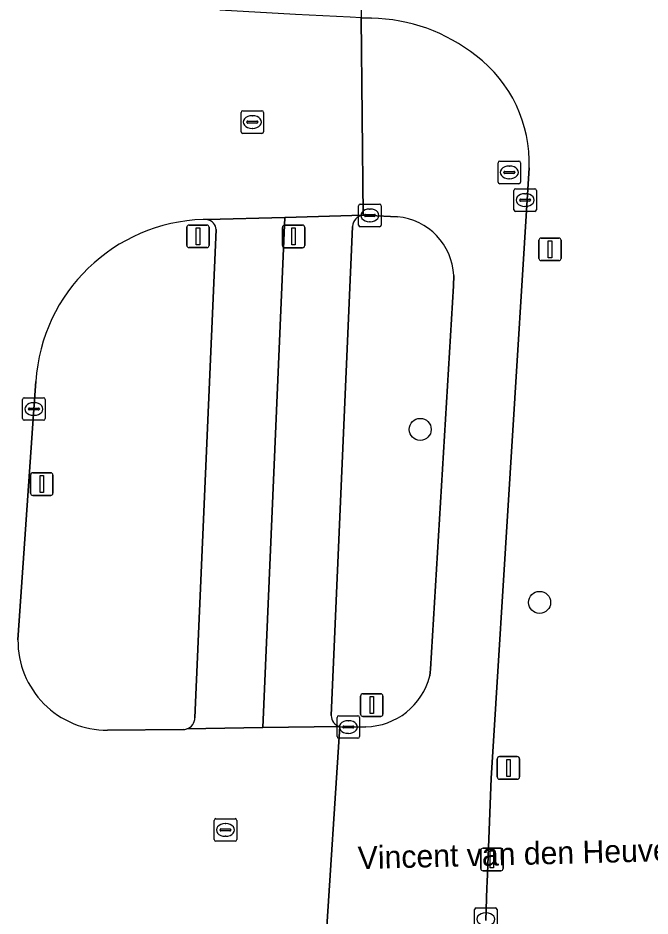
# Model space of a CAD drawing. Extents: x 161477 to 163040, y 383680 to 384871.
# Drawn here: x 161516.43 to 161544.45, y 384118.32 to 384158.1 of the extents above; entities that cross this region are included whole.
import ezdxf

# ---------------------------------------------------------------- set-up
doc = ezdxf.new("R2010")
doc.units = 0
for name, color, linetype in [('IMGEO_Afsluitpaal', 7, 'Continuous'), ('IMGEO_Boom', 7, 'Continuous'), ('IMGEO_Fietspad_open', 7, 'Continuous'), ('IMGEO_Groenvoorziening', 7, 'Continuous'), ('IMGEO_Kolk', 7, 'Continuous'), ('IMGEO_Lichtmast', 7, 'Continuous'), ('IMGEO_Openbare_ruimte_label', 7, 'Continuous'), ('IMGEO_Rijbaan_lokaal_gesloten', 7, 'Continuous'), ('IMGEO_Rioolput', 7, 'Continuous'), ('IMGEO_Verkeersbordpaal', 7, 'Continuous'), ('IMGEO_Verkeerseiland_groen', 7, 'Continuous'), ('IMGEO_Vlaggenmast', 7, 'Continuous'), ('IMGEO_Voetpad_open', 7, 'Continuous')]:
    doc.layers.add(name, color=color, linetype=linetype)

msp = doc.modelspace()

# ---------------------------------------------------------------- linework, layer by layer
at = {"layer": 'IMGEO_Afsluitpaal'}
for p, q in [((161537.045, 384121.33), (161537.835, 384121.33)), ((161537.835, 384121.33), (161537.045, 384121.33)), ((161536.945, 384120.43), (161536.945, 384121.23)), ((161536.945, 384121.23), (161536.945, 384120.43)), ((161537.935, 384121.23), (161537.935, 384120.43)), ((161537.935, 384120.43), (161537.935, 384121.23)), ((161537.835, 384120.33), (161537.045, 384120.33)), ((161537.045, 384120.33), (161537.835, 384120.33))]:
    msp.add_line(p, q, dxfattribs=at)
msp.add_lwpolyline([(161537.365, 384121.205), (161537.515, 384121.205), (161537.515, 384120.455), (161537.365, 384120.455), (161537.365, 384121.205)], dxfattribs=at)
for centre, start, end in [((161537.045, 384121.23), 90, 180), ((161537.045, 384121.23), 90, 180), ((161537.835, 384121.23), 0, 90), ((161537.835, 384121.23), 360, 90), ((161537.045, 384120.43), 180, 270), ((161537.045, 384120.43), 180, 270), ((161537.835, 384120.43), 270, 0), ((161537.835, 384120.43), 270, 0)]:
    msp.add_arc(centre, 0.1, start, end, dxfattribs=at)
at = {"layer": 'IMGEO_Boom'}
for centre in [(161534.259, 384139.873), (161539.548, 384132.212)]:
    msp.add_circle(centre, 0.489, dxfattribs=at)
at = {"layer": 'IMGEO_Fietspad_open'}
for points in [[(161523.918, 384126.609), (161527.282, 384126.677), (161528.268, 384149.264)], [(161528.268, 384149.264), (161524.815, 384149.17)], [(161525.225, 384148.724), (161524.274, 384127.108)]]:
    msp.add_lwpolyline(points, dxfattribs=at)
for centre, radius, start, end in [((161524.716, 384148.668), 0.512, 6.3303, 78.8532), ((161523.751, 384127.105), 0.523, 288.6131, 0.3768)]:
    msp.add_arc(centre, radius, start, end, dxfattribs=at)
at = {"layer": 'IMGEO_Groenvoorziening'}
for points in [[(161628.281, 384137.114), (161624.648, 384135.722), (161619.424, 384134.087), (161616.059, 384133.366), (161612.429, 384132.961), (161606.375, 384132.939), (161598.545, 384133.672), (161592.268, 384135.114), (161586.623, 384137.484), (161581.539, 384140.473), (161576.425, 384143.894), (161572.308, 384147.016), (161565.467, 384151.61), (161561.106, 384153.825), (161556.746, 384155.662), (161551.068, 384157.566), (161545.8, 384159.194), (161540.797, 384160.153), (161534.39, 384160.217), (161531.691, 384160.176), (161531.642, 384158.109), (161532.1, 384158.086)], [(161539.082, 384151.455), (161537.405, 384124.413), (161537.225, 384119.825), (161537.21, 384119.595), (161537.167, 384118.119)]]:
    msp.add_lwpolyline(points, dxfattribs=at)
for centre, radius, start, end in [((161531.982, 384150.476), 7.611, 51.3377, 89.1153), ((161533.182, 384151.704), 5.906, 357.5883, 52.9839)]:
    msp.add_arc(centre, radius, start, end, dxfattribs=at)
at = {"layer": 'IMGEO_Kolk'}
for p, q in [((161538.41, 384149.606), (161538.41, 384150.458)), ((161538.485, 384150.532), (161539.337, 384150.532)), ((161538.898, 384150.312), (161538.923, 384150.312)), ((161539.411, 384150.458), (161539.411, 384149.606)), ((161538.669, 384150.026), (161538.669, 384150.038)), ((161539.107, 384149.989), (161538.709, 384149.989)), ((161538.712, 384150.075), (161539.11, 384150.075)), ((161539.153, 384150.038), (161539.153, 384150.026)), ((161531.529, 384148.927), (161531.529, 384149.779)), ((161531.604, 384149.853), (161532.456, 384149.853)), ((161532.017, 384149.633), (161532.042, 384149.633)), ((161532.53, 384149.779), (161532.53, 384148.927)), ((161539.337, 384149.532), (161538.485, 384149.532)), ((161538.921, 384149.752), (161538.896, 384149.752)), ((161531.788, 384149.347), (161531.788, 384149.359)), ((161532.226, 384149.31), (161531.828, 384149.31)), ((161531.831, 384149.396), (161532.229, 384149.396)), ((161532.272, 384149.359), (161532.272, 384149.347)), ((161532.456, 384148.853), (161531.604, 384148.853)), ((161532.04, 384149.073), (161532.015, 384149.073)), ((161516.639, 384140.353), (161516.639, 384141.205)), ((161516.714, 384141.279), (161517.566, 384141.279)), ((161517.64, 384141.205), (161517.64, 384140.353)), ((161516.898, 384140.773), (161516.898, 384140.785)), ((161517.336, 384140.736), (161516.938, 384140.736)), ((161516.941, 384140.822), (161517.339, 384140.822)), ((161517.127, 384141.059), (161517.152, 384141.059)), ((161517.382, 384140.785), (161517.382, 384140.773)), ((161517.15, 384140.499), (161517.125, 384140.499)), ((161517.566, 384140.279), (161516.714, 384140.279)), ((161530.574, 384126.269), (161530.574, 384127.121)), ((161530.649, 384127.195), (161531.501, 384127.195)), ((161531.062, 384126.975), (161531.087, 384126.975)), ((161531.575, 384127.121), (161531.575, 384126.269)), ((161530.833, 384126.689), (161530.833, 384126.701)), ((161531.271, 384126.652), (161530.873, 384126.652)), ((161530.876, 384126.738), (161531.274, 384126.738)), ((161531.085, 384126.415), (161531.06, 384126.415)), ((161531.317, 384126.701), (161531.317, 384126.689)), ((161531.501, 384126.195), (161530.649, 384126.195)), ((161536.668, 384117.759), (161536.668, 384118.611)), ((161536.743, 384118.685), (161537.595, 384118.685)), ((161537.156, 384118.465), (161537.181, 384118.465)), ((161537.669, 384118.611), (161537.669, 384117.759))]:
    msp.add_line(p, q, dxfattribs=at)
for points in [[(161538.41, 384149.606), (161538.41, 384150.458)], [(161538.485, 384150.532), (161539.337, 384150.532)], [(161539.411, 384150.458), (161539.411, 384149.606)], [(161531.529, 384148.927), (161531.529, 384149.779)], [(161531.604, 384149.853), (161532.456, 384149.853)], [(161532.53, 384149.779), (161532.53, 384148.927)], [(161539.337, 384149.532), (161538.485, 384149.532)], [(161532.456, 384148.853), (161531.604, 384148.853)], [(161516.639, 384140.353), (161516.639, 384141.205)], [(161516.714, 384141.279), (161517.566, 384141.279)], [(161517.64, 384141.205), (161517.64, 384140.353)], [(161517.566, 384140.279), (161516.714, 384140.279)], [(161530.574, 384126.269), (161530.574, 384127.121)], [(161530.649, 384127.195), (161531.501, 384127.195)], [(161531.575, 384127.121), (161531.575, 384126.269)], [(161531.501, 384126.195), (161530.649, 384126.195)], [(161536.668, 384117.759), (161536.668, 384118.611)], [(161536.743, 384118.685), (161537.595, 384118.685)], [(161537.669, 384118.611), (161537.669, 384117.759)]]:
    msp.add_lwpolyline(points, dxfattribs=at)
for centre, radius, start, end in [((161538.487, 384150.456), 0.0765, 91.552, 178.448), ((161538.487, 384150.456), 0.0765, 91.552, 178.448), ((161539.335, 384150.456), 0.0765, 1.552, 88.448), ((161539.335, 384150.456), 0.0765, 1.552, 88.448), ((161538.709, 384150.035), 0.0403, 85.8775, 175.7526), ((161538.706, 384150.025), 0.0366, 178.938, 274.7102), ((161539.11, 384150.032), 0.043, 264.8664, 352.4533), ((161539.114, 384150.037), 0.0386, 1.7309, 96.639), ((161531.606, 384149.777), 0.0765, 91.552, 178.448), ((161531.606, 384149.777), 0.0765, 91.552, 178.448), ((161532.454, 384149.777), 0.0765, 1.552, 88.448), ((161532.454, 384149.777), 0.0765, 1.552, 88.448), ((161538.487, 384149.608), 0.0765, 181.552, 268.448), ((161538.487, 384149.608), 0.0765, 181.552, 268.448), ((161539.335, 384149.608), 0.0765, 271.552, 358.448), ((161539.335, 384149.608), 0.0765, 271.552, 358.448), ((161531.828, 384149.356), 0.0403, 85.8775, 175.7526), ((161531.825, 384149.346), 0.0366, 178.938, 274.7102), ((161532.229, 384149.353), 0.043, 264.8664, 352.4533), ((161532.233, 384149.358), 0.0386, 1.7309, 96.639), ((161531.606, 384148.929), 0.0765, 181.552, 268.448), ((161531.606, 384148.929), 0.0765, 181.552, 268.448), ((161532.454, 384148.929), 0.0765, 271.552, 358.448), ((161532.454, 384148.929), 0.0765, 271.552, 358.448), ((161516.716, 384141.203), 0.0765, 91.552, 178.448), ((161516.716, 384141.203), 0.0765, 91.552, 178.448), ((161517.564, 384141.203), 0.0765, 1.552, 88.448), ((161517.564, 384141.203), 0.0765, 1.552, 88.448), ((161516.938, 384140.782), 0.0403, 85.8775, 175.7526), ((161516.935, 384140.772), 0.0366, 178.938, 274.7102), ((161517.339, 384140.779), 0.043, 264.8664, 352.4533), ((161517.343, 384140.784), 0.0386, 1.7309, 96.639), ((161516.716, 384140.355), 0.0765, 181.552, 268.448), ((161516.716, 384140.355), 0.0765, 181.552, 268.448), ((161517.564, 384140.355), 0.0765, 271.552, 358.448), ((161517.564, 384140.355), 0.0765, 271.552, 358.448), ((161530.651, 384127.119), 0.0765, 91.552, 178.448), ((161530.651, 384127.119), 0.0765, 91.552, 178.448), ((161531.499, 384127.119), 0.0765, 1.552, 88.448), ((161531.499, 384127.119), 0.0765, 1.552, 88.448), ((161530.873, 384126.698), 0.0403, 85.8775, 175.7526), ((161530.87, 384126.688), 0.0366, 178.938, 274.7102), ((161531.274, 384126.695), 0.043, 264.8664, 352.4533), ((161531.278, 384126.7), 0.0386, 1.7309, 96.639), ((161530.651, 384126.271), 0.0765, 181.552, 268.448), ((161530.651, 384126.271), 0.0765, 181.552, 268.448), ((161531.499, 384126.271), 0.0765, 271.552, 358.448), ((161531.499, 384126.271), 0.0765, 271.552, 358.448), ((161536.745, 384118.609), 0.0765, 91.552, 178.448), ((161536.745, 384118.609), 0.0765, 91.552, 178.448), ((161537.593, 384118.609), 0.0765, 1.552, 88.448), ((161537.593, 384118.609), 0.0765, 1.552, 88.448)]:
    msp.add_arc(centre, radius, start, end, dxfattribs=at)
for centre, major_axis, ratio, start_param, end_param in [((161538.897, 384150.032), (-0.387, 0.002), 0.722429, 4.712389, 7.853982), ((161538.922, 384150.032), (-0.39, 0.002), 0.717154, 1.570796, 4.712389), ((161532.016, 384149.353), (-0.387, 0.002), 0.722429, 4.712389, 7.853982), ((161532.041, 384149.353), (-0.39, 0.002), 0.717154, 1.570796, 4.712389), ((161517.126, 384140.779), (-0.387, 0.002), 0.722429, 4.712389, 7.853982), ((161517.151, 384140.779), (-0.39, 0.002), 0.717154, 1.570796, 4.712389), ((161531.061, 384126.695), (-0.387, 0.002), 0.722429, 4.712389, 7.853982), ((161531.086, 384126.695), (-0.39, 0.002), 0.717154, 1.570796, 4.712389), ((161537.155, 384118.185), (-0.387, 0.002), 0.722429, 4.712389, 7.853982), ((161537.18, 384118.185), (-0.39, 0.002), 0.717154, 1.570796, 4.712389)]:
    msp.add_ellipse(centre, major_axis=major_axis, ratio=ratio, start_param=start_param, end_param=end_param, dxfattribs=at)
at = {"layer": 'IMGEO_Lichtmast'}
for p, q in [((161528.153, 384148.024), (161528.153, 384148.824)), ((161528.153, 384148.824), (161528.153, 384148.024)), ((161528.253, 384148.924), (161529.043, 384148.924)), ((161529.043, 384148.924), (161528.253, 384148.924)), ((161529.143, 384148.824), (161529.143, 384148.024)), ((161529.143, 384148.024), (161529.143, 384148.824)), ((161529.043, 384147.924), (161528.253, 384147.924)), ((161528.253, 384147.924), (161529.043, 384147.924)), ((161517.095, 384137.953), (161517.885, 384137.953)), ((161517.885, 384137.953), (161517.095, 384137.953)), ((161516.995, 384137.053), (161516.995, 384137.853)), ((161516.995, 384137.853), (161516.995, 384137.053)), ((161517.985, 384137.853), (161517.985, 384137.053)), ((161517.985, 384137.053), (161517.985, 384137.853)), ((161517.885, 384136.953), (161517.095, 384136.953)), ((161517.095, 384136.953), (161517.885, 384136.953))]:
    msp.add_line(p, q, dxfattribs=at)
for points in [[(161528.573, 384148.799), (161528.723, 384148.799), (161528.723, 384148.049), (161528.573, 384148.049), (161528.573, 384148.799)], [(161517.415, 384137.828), (161517.565, 384137.828), (161517.565, 384137.078), (161517.415, 384137.078), (161517.415, 384137.828)]]:
    msp.add_lwpolyline(points, dxfattribs=at)
for centre, start, end in [((161528.253, 384148.824), 90, 180), ((161528.253, 384148.824), 90, 180), ((161529.043, 384148.824), 0, 90), ((161529.043, 384148.824), 360, 90), ((161528.253, 384148.024), 180, 270), ((161528.253, 384148.024), 180, 270), ((161529.043, 384148.024), 270, 0), ((161529.043, 384148.024), 270, 0), ((161517.095, 384137.853), 90, 180), ((161517.095, 384137.853), 90, 180), ((161517.885, 384137.853), 0, 90), ((161517.885, 384137.853), 360, 90), ((161517.095, 384137.053), 180, 270), ((161517.095, 384137.053), 180, 270), ((161517.885, 384137.053), 270, 0), ((161517.885, 384137.053), 270, 0)]:
    msp.add_arc(centre, 0.1, start, end, dxfattribs=at)
at = {"layer": 'IMGEO_Rijbaan_lokaal_gesloten'}
for points in [[(161524.815, 384149.17), (161528.268, 384149.264), (161531.725, 384149.358), (161531.642, 384158.109), (161531.156, 384158.133), (161528.739, 384158.251), (161525.377, 384158.45)], [(161532.1, 384158.086), (161531.642, 384158.109), (161531.725, 384149.358), (161531.759, 384149.36), (161531.793, 384149.36), (161532.03, 384149.353), (161533.25, 384149.288)], [(161537.167, 384118.119), (161537.21, 384119.595), (161537.225, 384119.825), (161537.405, 384124.413), (161539.082, 384151.455)], [(161535.746, 384146.688), (161535.738, 384146.227), (161534.722, 384129.256), (161534.686, 384128.956)], [(161516.434, 384130.556), (161517.14, 384140.779), (161517.224, 384142.004)], [(161523.75, 384126.582), (161520.406, 384126.549)], [(161530.064, 384116.948), (161530.697, 384126.716), (161527.282, 384126.677), (161523.918, 384126.609)], [(161530.697, 384126.716), (161530.064, 384116.948)], [(161531.85, 384126.707), (161531.075, 384126.695), (161530.841, 384126.7)]]:
    msp.add_lwpolyline(points, dxfattribs=at)
for centre, radius, start, end in [((161531.982, 384150.476), 7.611, 51.3377, 89.1153), ((161533.182, 384151.704), 5.906, 357.5883, 52.9839), ((161524.896, 384141.489), 7.689, 91.8843, 176.1601), ((161524.717, 384148.647), 0.532, 79.3661, 97.9695), ((161533.014, 384146.564), 2.735, 2.6081, 85.0536), ((161520.403, 384130.518), 3.969, 179.456, 270.0414), ((161531.793, 384129.692), 2.985, 271.0957, 345.7344), ((161523.747, 384127.136), 0.554, 270.2901, 287.9703), ((161530.826, 384127.219), 0.519, 255.6373, 271.6824)]:
    msp.add_arc(centre, radius, start, end, dxfattribs=at)
at = {"layer": 'IMGEO_Rioolput'}
for p, q in [((161526.321, 384153.061), (161526.321, 384153.913)), ((161526.396, 384153.987), (161527.248, 384153.987)), ((161527.322, 384153.913), (161527.322, 384153.061)), ((161526.58, 384153.481), (161526.58, 384153.493)), ((161526.623, 384153.53), (161527.021, 384153.53)), ((161526.809, 384153.767), (161526.834, 384153.767)), ((161527.064, 384153.493), (161527.064, 384153.481)), ((161527.018, 384153.444), (161526.62, 384153.444)), ((161526.832, 384153.207), (161526.807, 384153.207)), ((161527.248, 384152.987), (161526.396, 384152.987)), ((161537.709, 384150.832), (161537.709, 384151.684)), ((161537.784, 384151.758), (161538.636, 384151.758)), ((161538.197, 384151.538), (161538.222, 384151.538)), ((161538.71, 384151.684), (161538.71, 384150.832)), ((161537.968, 384151.252), (161537.968, 384151.264)), ((161538.406, 384151.215), (161538.008, 384151.215)), ((161538.011, 384151.301), (161538.409, 384151.301)), ((161538.452, 384151.264), (161538.452, 384151.252)), ((161538.636, 384150.758), (161537.784, 384150.758)), ((161538.22, 384150.978), (161538.195, 384150.978)), ((161525.129, 384121.71), (161525.129, 384122.562)), ((161525.204, 384122.636), (161526.056, 384122.636)), ((161526.13, 384122.562), (161526.13, 384121.71)), ((161525.388, 384122.13), (161525.388, 384122.142)), ((161525.826, 384122.093), (161525.428, 384122.093)), ((161525.431, 384122.179), (161525.829, 384122.179)), ((161525.617, 384122.416), (161525.642, 384122.416)), ((161525.872, 384122.142), (161525.872, 384122.13)), ((161525.64, 384121.856), (161525.615, 384121.856)), ((161526.056, 384121.636), (161525.204, 384121.636))]:
    msp.add_line(p, q, dxfattribs=at)
for points in [[(161526.321, 384153.061), (161526.321, 384153.913)], [(161526.396, 384153.987), (161527.248, 384153.987)], [(161527.322, 384153.913), (161527.322, 384153.061)], [(161527.248, 384152.987), (161526.396, 384152.987)], [(161537.709, 384150.832), (161537.709, 384151.684)], [(161537.784, 384151.758), (161538.636, 384151.758)], [(161538.71, 384151.684), (161538.71, 384150.832)], [(161538.636, 384150.758), (161537.784, 384150.758)], [(161525.129, 384121.71), (161525.129, 384122.562)], [(161525.204, 384122.636), (161526.056, 384122.636)], [(161526.13, 384122.562), (161526.13, 384121.71)], [(161526.056, 384121.636), (161525.204, 384121.636)]]:
    msp.add_lwpolyline(points, dxfattribs=at)
for centre, radius, start, end in [((161526.398, 384153.911), 0.0765, 91.552, 178.448), ((161526.398, 384153.911), 0.0765, 91.552, 178.448), ((161527.246, 384153.911), 0.0765, 1.552, 88.448), ((161527.246, 384153.911), 0.0765, 1.552, 88.448), ((161526.62, 384153.49), 0.0403, 85.8775, 175.7526), ((161526.617, 384153.48), 0.0366, 178.938, 274.7102), ((161527.021, 384153.487), 0.043, 264.8664, 352.4533), ((161527.025, 384153.492), 0.0386, 1.7309, 96.639), ((161526.398, 384153.063), 0.0765, 181.552, 268.448), ((161526.398, 384153.063), 0.0765, 181.552, 268.448), ((161527.246, 384153.063), 0.0765, 271.552, 358.448), ((161527.246, 384153.063), 0.0765, 271.552, 358.448), ((161537.786, 384151.682), 0.0765, 91.552, 178.448), ((161537.786, 384151.682), 0.0765, 91.552, 178.448), ((161538.634, 384151.682), 0.0765, 1.552, 88.448), ((161538.634, 384151.682), 0.0765, 1.552, 88.448), ((161538.008, 384151.261), 0.0403, 85.8775, 175.7526), ((161538.005, 384151.251), 0.0366, 178.938, 274.7102), ((161538.409, 384151.258), 0.043, 264.8664, 352.4533), ((161538.413, 384151.263), 0.0386, 1.7309, 96.639), ((161537.786, 384150.834), 0.0765, 181.552, 268.448), ((161537.786, 384150.834), 0.0765, 181.552, 268.448), ((161538.634, 384150.834), 0.0765, 271.552, 358.448), ((161538.634, 384150.834), 0.0765, 271.552, 358.448), ((161525.206, 384122.56), 0.0765, 91.552, 178.448), ((161525.206, 384122.56), 0.0765, 91.552, 178.448), ((161526.054, 384122.56), 0.0765, 1.552, 88.448), ((161526.054, 384122.56), 0.0765, 1.552, 88.448), ((161525.428, 384122.139), 0.0403, 85.8775, 175.7526), ((161525.425, 384122.129), 0.0366, 178.938, 274.7102), ((161525.829, 384122.136), 0.043, 264.8664, 352.4533), ((161525.833, 384122.141), 0.0386, 1.7309, 96.639), ((161525.206, 384121.712), 0.0765, 181.552, 268.448), ((161525.206, 384121.712), 0.0765, 181.552, 268.448), ((161526.054, 384121.712), 0.0765, 271.552, 358.448), ((161526.054, 384121.712), 0.0765, 271.552, 358.448)]:
    msp.add_arc(centre, radius, start, end, dxfattribs=at)
for centre, major_axis, ratio, start_param, end_param in [((161526.808, 384153.487), (-0.387, 0.002), 0.722429, 4.712389, 7.853982), ((161526.833, 384153.487), (-0.39, 0.002), 0.717154, 1.570796, 4.712389), ((161538.196, 384151.258), (-0.387, 0.002), 0.722429, 4.712389, 7.853982), ((161538.221, 384151.258), (-0.39, 0.002), 0.717154, 1.570796, 4.712389), ((161525.616, 384122.136), (-0.387, 0.002), 0.722429, 4.712389, 7.853982), ((161525.641, 384122.136), (-0.39, 0.002), 0.717154, 1.570796, 4.712389)]:
    msp.add_ellipse(centre, major_axis=major_axis, ratio=ratio, start_param=start_param, end_param=end_param, dxfattribs=at)
at = {"layer": 'IMGEO_Verkeersbordpaal'}
for p, q in [((161523.917, 384148.026), (161523.917, 384148.826)), ((161523.917, 384148.826), (161523.917, 384148.026)), ((161524.017, 384148.926), (161524.807, 384148.926)), ((161524.807, 384148.926), (161524.017, 384148.926)), ((161524.907, 384148.826), (161524.907, 384148.026)), ((161524.907, 384148.026), (161524.907, 384148.826)), ((161524.807, 384147.926), (161524.017, 384147.926)), ((161524.017, 384147.926), (161524.807, 384147.926)), ((161531.62, 384127.266), (161531.62, 384128.066)), ((161531.62, 384128.066), (161531.62, 384127.266)), ((161531.72, 384128.166), (161532.51, 384128.166)), ((161532.51, 384128.166), (161531.72, 384128.166)), ((161532.61, 384128.066), (161532.61, 384127.266)), ((161532.61, 384127.266), (161532.61, 384128.066)), ((161532.51, 384127.166), (161531.72, 384127.166)), ((161531.72, 384127.166), (161532.51, 384127.166)), ((161537.672, 384124.484), (161537.672, 384125.284)), ((161537.672, 384125.284), (161537.672, 384124.484)), ((161537.772, 384125.384), (161538.562, 384125.384)), ((161538.562, 384125.384), (161537.772, 384125.384)), ((161538.662, 384125.284), (161538.662, 384124.484)), ((161538.662, 384124.484), (161538.662, 384125.284)), ((161538.562, 384124.384), (161537.772, 384124.384)), ((161537.772, 384124.384), (161538.562, 384124.384))]:
    msp.add_line(p, q, dxfattribs=at)
for points in [[(161524.337, 384148.801), (161524.487, 384148.801), (161524.487, 384148.051), (161524.337, 384148.051), (161524.337, 384148.801)], [(161532.04, 384128.041), (161532.19, 384128.041), (161532.19, 384127.291), (161532.04, 384127.291), (161532.04, 384128.041)], [(161538.092, 384125.259), (161538.242, 384125.259), (161538.242, 384124.509), (161538.092, 384124.509), (161538.092, 384125.259)]]:
    msp.add_lwpolyline(points, dxfattribs=at)
for centre, start, end in [((161524.017, 384148.826), 90, 180), ((161524.017, 384148.826), 90, 180), ((161524.807, 384148.826), 0, 90), ((161524.807, 384148.826), 360, 90), ((161524.017, 384148.026), 180, 270), ((161524.017, 384148.026), 180, 270), ((161524.807, 384148.026), 270, 0), ((161524.807, 384148.026), 270, 0), ((161531.72, 384128.066), 90, 180), ((161531.72, 384128.066), 90, 180), ((161532.51, 384128.066), 0, 90), ((161532.51, 384128.066), 360, 90), ((161531.72, 384127.266), 180, 270), ((161531.72, 384127.266), 180, 270), ((161532.51, 384127.266), 270, 0), ((161532.51, 384127.266), 270, 0), ((161537.772, 384125.284), 90, 180), ((161537.772, 384125.284), 90, 180), ((161538.562, 384125.284), 0, 90), ((161538.562, 384125.284), 360, 90), ((161537.772, 384124.484), 180, 270), ((161537.772, 384124.484), 180, 270), ((161538.562, 384124.484), 270, 0), ((161538.562, 384124.484), 270, 0)]:
    msp.add_arc(centre, 0.1, start, end, dxfattribs=at)
at = {"layer": 'IMGEO_Verkeerseiland_groen'}
for points in [[(161533.25, 384149.288), (161532.03, 384149.353), (161531.793, 384149.36), (161531.759, 384149.36), (161531.725, 384149.358)], [(161524.274, 384127.108), (161525.225, 384148.724)], [(161531.263, 384148.863), (161530.314, 384127.202)], [(161534.686, 384128.956), (161534.722, 384129.256), (161535.738, 384146.227), (161535.746, 384146.688)], [(161517.224, 384142.004), (161517.14, 384140.779), (161516.434, 384130.556)], [(161520.406, 384126.549), (161523.75, 384126.582)], [(161530.841, 384126.7), (161531.075, 384126.695), (161531.85, 384126.707)]]:
    msp.add_lwpolyline(points, dxfattribs=at)
for centre, radius, start, end in [((161524.896, 384141.489), 7.689, 91.8843, 176.1601), ((161524.717, 384148.647), 0.532, 79.3661, 97.9695), ((161524.716, 384148.668), 0.512, 6.3303, 78.8532), ((161531.773, 384148.851), 0.51, 95.3479, 178.6019), ((161533.014, 384146.564), 2.735, 2.6081, 85.0536), ((161520.403, 384130.518), 3.969, 179.456, 270.0414), ((161531.793, 384129.692), 2.985, 271.0957, 345.7344), ((161523.751, 384127.105), 0.523, 288.6131, 0.3768), ((161530.822, 384127.208), 0.508, 180.7023, 255.7786), ((161523.747, 384127.136), 0.554, 270.2901, 287.9703), ((161530.826, 384127.219), 0.519, 255.6373, 271.6824)]:
    msp.add_arc(centre, radius, start, end, dxfattribs=at)
at = {"layer": 'IMGEO_Vlaggenmast'}
for p, q in [((161539.617, 384148.35), (161540.407, 384148.35)), ((161540.407, 384148.35), (161539.617, 384148.35)), ((161539.517, 384147.45), (161539.517, 384148.25)), ((161539.517, 384148.25), (161539.517, 384147.45)), ((161540.507, 384148.25), (161540.507, 384147.45)), ((161540.507, 384147.45), (161540.507, 384148.25)), ((161540.407, 384147.35), (161539.617, 384147.35)), ((161539.617, 384147.35), (161540.407, 384147.35))]:
    msp.add_line(p, q, dxfattribs=at)
msp.add_lwpolyline([(161539.937, 384148.225), (161540.087, 384148.225), (161540.087, 384147.475), (161539.937, 384147.475), (161539.937, 384148.225)], dxfattribs=at)
for centre, start, end in [((161539.617, 384148.25), 90, 180), ((161539.617, 384148.25), 90, 180), ((161540.407, 384148.25), 0, 90), ((161540.407, 384148.25), 360, 90), ((161539.617, 384147.45), 180, 270), ((161539.617, 384147.45), 180, 270), ((161540.407, 384147.45), 270, 0), ((161540.407, 384147.45), 270, 0)]:
    msp.add_arc(centre, 0.1, start, end, dxfattribs=at)
at = {"layer": 'IMGEO_Voetpad_open'}
for points in [[(161531.725, 384149.358), (161528.268, 384149.264), (161527.282, 384126.677), (161530.697, 384126.716)], [(161530.314, 384127.202), (161531.263, 384148.863)]]:
    msp.add_lwpolyline(points, dxfattribs=at)
for centre, radius, start, end in [((161531.773, 384148.851), 0.51, 95.3479, 178.6019), ((161530.822, 384127.208), 0.508, 180.7023, 255.7786)]:
    msp.add_arc(centre, radius, start, end, dxfattribs=at)

# ---------------------------------------------------------------- texts
at = {"layer": 'IMGEO_Openbare_ruimte_label'}
msp.add_text('Vincent van den Heuvellaan', height=1, rotation=1.4894, dxfattribs=at).set_placement((161531.505, 384120.401))

doc.saveas('drawing.dxf')
